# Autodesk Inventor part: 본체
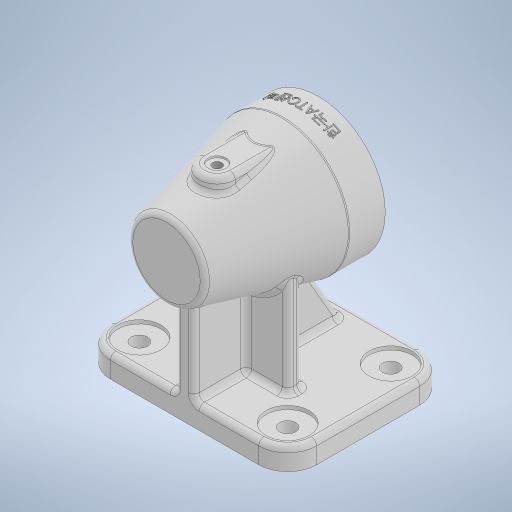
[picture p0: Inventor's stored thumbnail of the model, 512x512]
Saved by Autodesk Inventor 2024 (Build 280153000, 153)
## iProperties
Created: 2024-12
Part Number: 본체
Material: 일반
Document SubType Name: Modeling
Designer: user
Density: 1 g/cm^3
Appearance: 기본값
Author: user
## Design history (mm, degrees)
sketch "스케치11"
  geometry: L1 (0, 42)-(0, -42); L2 (0, 42)-(21, 42); L3 (21, 42)-(37, -22); L4 (37, -22)-(37, -42); L5 (37, -42)-(24.5, -42); L6 (23.5, -41)-(23.5, -24); L7 (23.5, -24)-(25.743, -24); L8 (30.606, -17.837)-(21.871, 18.698); L9 (18.953, 21)-(18.5, 21); L10 (17.5, 22)-(17.5, 30.7); L11 (17.2, 31)-(15.5, 31); L12 (15.5, 31)-(15.5, 31); L13 (12.5, 34)-(0, 34); L14 (17.5, 22)-(18.5, 21); L15 (23.5, -41)-(24.5, -42); L16 (24.5, -42)-(0, -42); A1 r 5 centre (25.743, -19) between (25.743, -24) and (30.606, -17.837); A2 r 0.3 centre (17.2, 30.7) between (17.5, 30.7) and (17.2, 31); A3 r 3 centre (18.953, 18) between (21.871, 18.698) and (18.953, 21); A4 r 3 centre (12.5, 31) between (15.5, 31) and (12.5, 34); 12 further points
  constraints: 32 end point, 8 perpendicular, 8 point on circle, 8 point on line, 8 tangent, 7 midpoint, 4 centre point, 2 vertical, 1 coincident, 1 horizontal, 1 parallel
  dimensions: "d29" = 84 distance of L1.start L1.end; "d30" = 74 diameter of L4 L1; "d31" = 42 diameter of L2.end L1; "d32" = 20 distance of L3.end L4.end; "d52" = 47 diameter of L6 L1; "d53" = 5 radius of A1; "d54" = 18 distance of point (23.5, -42) L6.end; "d56" = 35 diameter of point (17.5, 26.35) L1; "d57" = 31 diameter of point (15.5, 31) L1; "d58" = 0.3 radius of A2; "d59" = 10 distance from line of L9 point (16.35, 31); "d60" = 3 distance between parallel lines of L13 L11; "d62" = 3 radius of A3; "d63" = 5 distance from line of L3 point (26.239, 0.43); "d65" = 45 distance between parallel lines of L7 L9; "d66" = 3 radius of A4 (derived); "d67" = 1 distance of L10.start point (17.5, 21); "d68" = 1 distance of L9.end point (17.5, 21) (= d67); "d69" = 13.4469 deg angle of L1 L8; "d70" = 1 distance of L6.start point (23.5, -42); "d71" = 1 distance of L5.end point (23.5, -42) (= d70)
revolve "회전1" stored, may be unused: angle "d33" = 90 deg
node "작업 평면5"
sketch "스케치12"
  geometry: L1 (57, -57)-(-57, -57); L2 (-57, -57)-(-57, 32); L3 (-57, 32)-(57, 32); L4 (57, 32)-(57, -57); L5 (-37, -42)-(37, -42) reference; 2 further points
  constraints: 8 end point, 2 parallel, 1 horizontal, 1 midpoint, 1 perpendicular, 1 vertical alignment
  dimensions: "d35" = 15 distance between parallel lines of L5 L1; "d36" = 114 distance between parallel lines of L2 L4; "d37" = 89 distance of L1.end L2.end
extrude "돌출5" join sketch "스케치12" distance "d38" = 12; taper "d39" = 0 deg
revolve "회전2" stored, may be unused: angle "d72" = 90 deg
sketch "스케치18"
  geometry: L1 (-57, -32)-(57, -32) reference; L2 (-28, -3)-(28, -3); L3 (28, -3)-(28, 5); L4 (28, 5)-(-28, 5); L5 (-28, 5)-(-28, -3); 2 further points
  constraints: 8 end point, 2 parallel, 1 horizontal, 1 midpoint, 1 perpendicular, 1 vertical alignment
  dimensions: "d75" = 8 distance of L4.end L2.start; "d76" = 56 distance of L3.end L4.end; "d77" = 29 distance between parallel lines of L1 L2
extrude "돌출7" join sketch "스케치18" stored distance "d78" = 18; taper "d79" = 0 deg
sketch "스케치19"
  geometry: L1 (-37, -30.947)-(-70, -50); L2 (-70, -57)-(-70, 32) reference; L3 (-37, -22)-(-37, -42) reference; 1 further point
  constraints: 2 end point, 2 point on line
  dimensions: "d80" = 7 distance of L1.end L2.start; "d81" = 60 deg angle of L2 L1
feature "리브1" sketch "스케치19" dims "d82" = 1, "d83" = 10, "d84" = 0, "d85" = 0, "d86" = 1, "d87" = 1
sketch "스케치20"
  geometry: L1 (-82, 32)-(-70, 32) reference; L2 (-70, 32)-(-23.5, 32); L3 (-21, 42)-(-30.75, 3) reference; 1 further point
  constraints: 2 end point, 1 horizontal, 1 point on line
feature "리브2" sketch "스케치20" dims "d88" = 1, "d89" = 10, "d90" = 0, "d91" = 0, "d92" = 1, "d93" = 1
sketch "스케치21" dims "d94" = 57
  geometry: C1 r 24.5 at (0, 0) reference; C2 r 37 at (0, 0) reference; 2 further points
  constraints: 2 vertical alignment, 1 coincident, 2 other
hole "구멍1" sketch "스케치21" at (0, 28.5) diameter "d95" = 3.242; stored, may be unused: countersink angle "d99" = 90 deg, drill point angle "d101" = 118 deg; dims "d96" = 8, "d97" = 4, "d98" = 2, "d100" = 10
node "작업 평면6"
sketch "스케치22"
  geometry: L1 (-37, -42)-(37, -42) reference; L2 (16.733, -22)-(16.733, -42) reference; L3 (16.733, -42)-(-16.733, -42) reference; L4 (-16.733, -42)-(-16.733, -22) reference; L5 (10, 14)-(10, -11.928); L6 (-10, 14)-(-10, -11.928); L7 (5, 32)-(5, 3) reference; A1 r 10 centre (0, 14) between (10, 14) and (-10, 14); 1 further point
  constraints: 4 end point, 2 point on circle, 2 tangent, 1 centre point, 1 parallel, 1 vertical, 1 vertical alignment, 3 other
  dimensions: "d107" = 20 diameter of A1; "d108" = 56 distance from line of L1 A1.centre
extrude "돌출8" join sketch "스케치22" stored distance "d109" = 10; taper "d110" = 0 deg
fillet "모깎기1" dims "d111" = 3
fillet "모깎기2" dims "d112" = 3
sketch "스케치23"
  geometry: A1 r 7 centre (0, -14) between (-7, -14) and (7, -14) reference; 2 further points
  constraints: 1 coincident
hole "구멍2" sketch "스케치23" at (0, -14) diameter "d113" = 5.1881; stored, may be unused: countersink angle "d117" = 90 deg, drill point angle "d119" = 0 deg; dims "d114" = 12, "d115" = 10, "d116" = 1, "d118" = 17.1
fillet "모깎기3" dims "d120" = 16
sketch "스케치24"
  geometry: A1 r 16 centre (-41, -16) between (-57, -16) and (-41, -32) reference; A2 r 16 centre (41, -16) between (41, -32) and (57, -16) reference; A3 r 16 centre (41, 41) between (57, 41) and (41, 57) reference; A4 r 16 centre (-41, 41) between (-41, 57) and (-57, 41) reference; 5 further points
  constraints: 4 coincident
hole "구멍3" sketch "스케치24" at (41, 41), (41, -16), (-41, -16), (-41, 41) diameter "d121" = 9; stored, may be unused: countersink angle "d125" = 90 deg, drill point angle "d127" = 0 deg; dims "d122" = 12, "d123" = 24, "d124" = 2, "d126" = 8
fillet "모깎기4" dims "d128" = 3
fillet "모깎기5" dims "d129" = 3
fillet "모깎기6" dims "d130" = 3
fillet "모깎기7" dims "d131" = 3
node "작업 평면8"
sketch "스케치25"
  geometry: L1 (-37, -10)-(37, -10) reference; 2 further points
  constraints: 1 vertical alignment, 1 other
  dimensions: "d137" = 9 distance from line of L1 point (0, -1)
feature "엠보싱1" sketch "스케치25" dims "d29" = 84, "d30" = 74, "d31" = 42, "d32" = 20, "d52" = 47, "d53" = 5, "d54" = 18, "d56" = 35, "d57" = 31, "d58" = 0.3, "d59" = 10, "d60" = 3, "d62" = 3, "d63" = 5, "d65" = 45, "d66" = 3 (derived), "d67" = 1, "d68" = 1 (= d67), "d69" = 2.34693, "d70" = 1, "d71" = 1 (= d70), "d134" = 0.5, "d135" = 0
fillet "모깎기8" dims "d136" = 3
feature "Ϧ耀Ϩ耀Ϫ耀Ϭ耀Ϯ耀ϰ耀ϲ耀ϴ耀" dims "d29" = 84, "d30" = 74, "d31" = 42, "d32" = 20, "d33" = 90 deg, "d34" = -82, "d35" = 15, "d36" = 114, "d37" = 89, "d38" = 12, "d39" = 0, "d52" = 47, "d53" = 5, "d54" = 18, "d56" = 35, "d57" = 31, "d58" = 0.3, "d59" = 10, "d60" = 3, "d62" = 3, "d63" = 5, "d65" = 45, "d66" = 3 (derived), "d67" = 1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
node "솔리드3"
pattern_circular "원형 패턴1" dims angle "d103" = 360 deg
node "절단 모서리 투영1"
feature "A9D066F2-1C7D-4E18-AEED-F7BC21143FA4" dims "d121" = 9, "d122" = 12, "d123" = 24, "d124" = 2, "d125" = 90 deg, "d126" = 8, "d127" = 0
